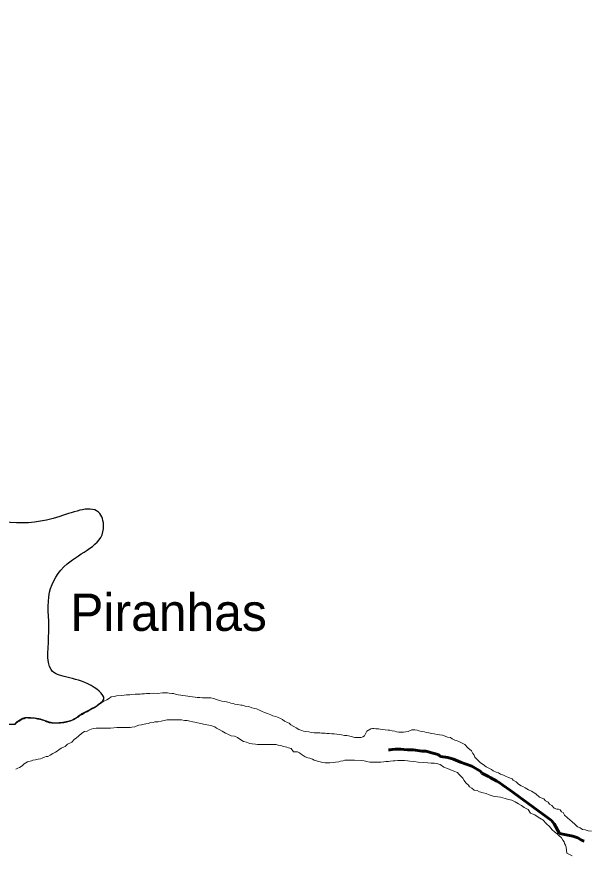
# Model space of a CAD drawing. Extents: x 553962 to 842807, y 8883888 to 9032388.
# Drawn here: x 635696 to 643403, y 8933785 to 8945035 of the extents above; entities that cross this region are included whole.
import ezdxf

# ---------------------------------------------------------------- set-up
doc = ezdxf.new("R2010")
doc.units = 0
doc.header["$LTSCALE"] = 200
doc.linetypes.add('LONG_DASH_SHORT_DASH', pattern=[9.9, 6, -1.2, 1.5, -1.2])
for name, color, linetype, lineweight in [('21', 7, 'Continuous', 25), ('25', 7, 'Continuous', 13), ('7', 7, 'Continuous', 90), ('9', 7, 'Continuous', 90)]:
    doc.layers.add(name, color=color, linetype=linetype, lineweight=lineweight)
doc.layers.add('41', color=7, linetype='Continuous')

msp = doc.modelspace()

# ---------------------------------------------------------------- linework, layer by layer
at = {"layer": '21'}
msp.add_spline([(635677.5, 8935542.3), (635110.6, 8935620.5), (634836.9, 8935855.3), (634709.8, 8936099.8), (634846.6, 8936275.8), (634973.7, 8936735.4), (635032.4, 8937263.6), (634739.1, 8937449.4), (634426.3, 8937517.8), (634700, 8937928.6), (634700, 8938261.1), (634533.8, 8938671.9), (634641.4, 8938906.6), (634768.4, 8938867.5), (634866.2, 8938740.3), (635130.1, 8938750.1), (635188.8, 8938564.3), (635325.6, 8938329.6), (635609.1, 8938251.3), (636273.8, 8938329.6), (636811.4, 8938368.7), (636860.3, 8938163.3), (636371.5, 8937693.9), (636136.9, 8937312.5), (636127.2, 8936784.3), (636156.5, 8936275.8), (636694.1, 8936060.6), (636850.5, 8935855.3), (636821.3, 8935831.4), (636756.6, 8935782.4), (636679.7, 8935742.2), (636611.5, 8935703.8), (636571.3, 8935684.5), (636504.8, 8935639.1), (636420.9, 8935593.6), (636337, 8935576.1), (636239.1, 8935562.1), (636151.7, 8935569.1), (636071.2, 8935593.6), (635990.8, 8935618.1), (635878.9, 8935632.1), (635826.5, 8935633.8), (635795, 8935628.6), (635758.3, 8935612.8), (635712.8, 8935584.8), (635680.9, 8935555.9), (635677.5, 8935542.3)], degree=3, dxfattribs=at)
at = {"layer": '25'}
for points in [[(635685.7, 8935554.4), (635710.8, 8935574.3), (635733.4, 8935581.6), (635756.1, 8935601.5), (635776.2, 8935611.4), (635796.2, 8935616.2), (635818.8, 8935626.1), (635848.8, 8935625.9), (635868.8, 8935625.8), (635908.8, 8935623), (635941.3, 8935617.8), (635973.8, 8935612.6), (636006.2, 8935604.8), (636036.2, 8935597.1), (636073.6, 8935586.9), (636096, 8935574.2), (636130.9, 8935559), (636165.9, 8935556.2), (636185.9, 8935556.1), (636205.9, 8935556), (636243.4, 8935555.7), (636263.5, 8935558.1), (636283.5, 8935557.9), (636303.5, 8935560.3), (636326, 8935562.7), (636346.1, 8935565), (636366.1, 8935569.9), (636398.7, 8935579.7), (636418.7, 8935582.1), (636456.4, 8935599.4), (636479, 8935616.7), (636519.2, 8935636.5), (636539.3, 8935653.9), (636579.5, 8935671.2), (636602.1, 8935691), (636642.3, 8935710.8), (636675, 8935730.6), (636712.6, 8935747.9), (636737.7, 8935762.7), (636770.4, 8935785.1), (636793.1, 8935802.4), (636835.8, 8935834.7), (636863.5, 8935852), (636906.1, 8935869.3), (636941.3, 8935891.6), (636964, 8935908.9), (637009, 8935916.2), (637036.6, 8935923.5), (637099.2, 8935928.1), (637136.7, 8935930.3), (637169.2, 8935935.1), (637214.3, 8935937.3), (637241.8, 8935942.2), (637284.4, 8935946.9), (637304.4, 8935946.8), (637351.9, 8935946.4), (637374.4, 8935948.8), (637412, 8935951.1), (637437, 8935953.4), (637479.5, 8935955.6), (637524.6, 8935960.3), (637584.6, 8935954.9), (637652.2, 8935962), (637672.2, 8935961.8), (637694.7, 8935961.7), (637719.7, 8935961.5), (637742.2, 8935958.9), (637777.1, 8935953.6), (637799.7, 8935953.5), (637824.6, 8935945.8), (637859.6, 8935938.1), (637897, 8935932.8), (637922, 8935927.6), (637959.5, 8935922.4), (637989.5, 8935917.2), (638012, 8935914.5)], [(638012, 8935914.5), (638051.9, 8935909.3), (638091.9, 8935904), (638116.9, 8935901.3), (638154.4, 8935901.1), (638186.9, 8935898.3), (638226.9, 8935895.6), (638259.4, 8935895.4), (638281.9, 8935895.2), (638301.9, 8935895.1), (638341.9, 8935887.3), (638376.8, 8935874.6), (638414.2, 8935861.8), (638449.2, 8935851.6), (638486.6, 8935846.3), (638509.1, 8935841.1), (638544.1, 8935835.9), (638566.5, 8935825.7), (638599, 8935820.5), (638621.5, 8935812.9), (638663.9, 8935805.1), (638701.4, 8935799.8), (638721.4, 8935799.7), (638761.3, 8935786.9), (638808.8, 8935779.1), (638851.2, 8935763.8), (638891.1, 8935753.5), (638913.6, 8935750.8), (638951, 8935733.1), (638978.4, 8935717.9), (639020.8, 8935700.1), (639058.2, 8935684.8), (639103.1, 8935669.5), (639130.5, 8935656.8), (639170.4, 8935646.5), (639195.4, 8935636.3), (639232.7, 8935618.6), (639260.2, 8935605.8), (639290, 8935583.1), (639327.4, 8935565.3), (639349.8, 8935555.2), (639374.7, 8935535), (639412, 8935512.2), (639444.4, 8935494.5), (639481.7, 8935471.7), (639519.2, 8935458.9), (639544.1, 8935451.3), (639576.6, 8935443.5), (639614, 8935438.3), (639646.5, 8935433.1), (639686.5, 8935427.8), (639719, 8935425.1), (639739, 8935424.9), (639761.5, 8935424.8), (639784, 8935422.1), (639814, 8935421.9), (639834, 8935421.8), (639856.5, 8935419.1), (639889, 8935416.4), (639921.5, 8935413.7), (639956.5, 8935413.5), (639991.5, 8935408.2), (640021.5, 8935405.5), (640053.9, 8935400.3), (640093.9, 8935392.5), (640126.4, 8935389.8), (640148.9, 8935384.7), (640183.8, 8935376.9), (640233.7, 8935364.2), (640316.3, 8935366), (640339.2, 8935375.1), (640361.5, 8935385.8), (640394.5, 8935450.6), (640447.2, 8935480.3), (640467.3, 8935485.2), (640487.3, 8935485.1), (640514.8, 8935482.4), (640549.8, 8935479.7), (640572.2, 8935474.5), (640607.2, 8935471.8), (640639.7, 8935466.5), (640677.2, 8935463.8), (640699.7, 8935461.1), (640732.2, 8935455.9), (640767.1, 8935450.7), (640789.6, 8935440.5), (640822, 8935435.3), (640842.1, 8935435.2), (640864.6, 8935435), (640884.6, 8935434.9), (640947.2, 8935447), (640994.9, 8935466.7), (641014.9, 8935466.6), (641037.4, 8935466.4), (641067.3, 8935461.2), (641089.8, 8935453.6), (641132.3, 8935445.8), (641167.2, 8935440.5), (641189.7, 8935432.8), (641224.7, 8935427.6), (641259.6, 8935419.9)], [(638992.5, 8935272.2), (638970, 8935272.3), (638925, 8935272.6), (638897.5, 8935275.3), (638855, 8935278.1), (638825, 8935285.8), (638777.6, 8935303.6), (638737.7, 8935311.4), (638700.3, 8935331.7), (638658.1, 8935364.5), (638618.2, 8935382.3), (638573.2, 8935387.6), (638535.8, 8935402.8), (638495.9, 8935423.1), (638451.1, 8935451), (638413.8, 8935471.2), (638376.4, 8935489), (638351.5, 8935506.7), (638314.1, 8935522), (638274.1, 8935529.8), (638224.2, 8935537.6), (638161.8, 8935553), (638086.8, 8935568.6), (638059.4, 8935576.2), (638019.4, 8935581.5), (637982, 8935591.8), (637947, 8935594.5), (637907, 8935599.8), (637884.5, 8935599.9), (637847, 8935600.2), (637827, 8935600.3), (637792, 8935600.5), (637754.5, 8935600.8), (637714.4, 8935601.1), (637691.9, 8935596.2), (637654.3, 8935588.9), (637631.8, 8935584.1), (637591.7, 8935576.8), (637549.2, 8935574.6), (637524.1, 8935567.3), (637481.5, 8935560), (637461.5, 8935552.7), (637426.4, 8935547.9), (637406.4, 8935543), (637371.3, 8935535.7), (637336.2, 8935528.4), (637298.6, 8935516.2), (637278.5, 8935508.8), (637238.5, 8935504.1), (637215.9, 8935499.2), (637180.9, 8935499.4), (637135.9, 8935499.7), (637105.9, 8935499.9), (637063.4, 8935500.2), (637040.8, 8935497.9), (637000.8, 8935493.1), (636955.8, 8935490.9), (636930.8, 8935491.1), (636890.7, 8935488.8), (636868.2, 8935489), (636830.7, 8935489.2), (636810.7, 8935489.4), (636780.7, 8935489.6), (636760.7, 8935489.7), (636725.6, 8935484.9), (636693, 8935475.1), (636673, 8935467.8), (636640.3, 8935447.9), (636605.2, 8935443.2), (636567.6, 8935420.9), (636524.7, 8935381.1), (636499.6, 8935358.7), (636466.9, 8935336.4), (636436.6, 8935301.6), (636416.5, 8935294.2), (636378.9, 8935276.9), (636343.6, 8935244.6), (636323.5, 8935234.7), (636293.4, 8935219.9), (636260.8, 8935200.1), (636238.1, 8935180.2), (636215.5, 8935167.8), (636180.3, 8935148.1), (636142.7, 8935128.3), (636112.5, 8935110.9), (636092.5, 8935108.6), (636069.9, 8935098.7), (636037.3, 8935088.9), (636014.7, 8935079.1), (635982.2, 8935074.3), (635947.1, 8935067), (635912, 8935059.7), (635892, 8935052.3), (635859.4, 8935042.5), (635839.3, 8935037.7), (635816.7, 8935025.3), (635794.1, 8935010.4), (635773.9, 8934990.5), (635753.8, 8934975.6), (635731.2, 8934963.3), (635708.6, 8934950.9)], [(641259.6, 8935419.9), (641294.6, 8935414.6), (641334.5, 8935404.4), (641369.5, 8935399.1), (641409.5, 8935393.8), (641441.9, 8935383.6), (641474.3, 8935368.4), (641514.3, 8935363.1), (641536.7, 8935345.4), (641574.1, 8935330.2), (641596.6, 8935325), (641636.4, 8935307.2), (641673.8, 8935289.5), (641708.7, 8935271.7), (641748.3, 8935223.9), (641798.1, 8935183.5), (641812.8, 8935148.3), (641832.6, 8935125.7), (641842.5, 8935100.6), (641872.2, 8935067.8), (641894.6, 8935047.7), (641916.9, 8935022.5), (641954.2, 8935002.2), (641994, 8934971.9), (642028.9, 8934954.1), (642063.8, 8934936.4), (642086.2, 8934918.7), (642126, 8934898.4), (642161, 8934890.7), (642188.4, 8934873), (642225.8, 8934860.2), (642260.7, 8934842.4), (642283.1, 8934832.3), (642318, 8934819.5), (642340.5, 8934811.9), (642357.8, 8934791.7), (642395.2, 8934769), (642427.4, 8934736.2), (642462.3, 8934715.9), (642484.8, 8934708.3), (642517.1, 8934690.5), (642539.5, 8934675.4), (642561.9, 8934660.2), (642604.3, 8934642.4), (642661.6, 8934609.5), (642711.2, 8934564.1), (642766.1, 8934543.7), (642790.9, 8934513.5), (642825.8, 8934495.7), (642845.6, 8934470.6), (642875.5, 8934450.3), (642907.7, 8934417.6), (642942.6, 8934402.3), (642965.1, 8934402.2), (642987.6, 8934394.5), (643004.9, 8934366.9), (643027.3, 8934356.7), (643044.6, 8934324), (643084.3, 8934286.2), (643146.4, 8934233.2), (643183.7, 8934202.9), (643221, 8934167.7), (643253.4, 8934152.4), (643288.2, 8934132.2), (643323.2, 8934124.4), (643363.1, 8934114.1), (643405.6, 8934108.8)], [(642690, 8934297.2), (642645.2, 8934327.5), (642587.9, 8934347.9), (642556.4, 8934400.2), (642504.8, 8934424.3), (642466.9, 8934451.8), (642425.6, 8934475.9), (642384.3, 8934503.4), (642339.5, 8934524.1), (642294.8, 8934534.4), (642294.8, 8934534.4), (642246.6, 8934548.2), (642188.1, 8934561.9), (642151.8, 8934566.1), (642086.9, 8934579), (642032, 8934596.9), (641994.6, 8934612.2), (641952.2, 8934620), (641902.2, 8934635.3), (641874.9, 8934653.1), (641834.9, 8934658.3), (641800.1, 8934686.1), (641770.2, 8934701.3), (641755.4, 8934726.4), (641723.1, 8934756.7), (641698.3, 8934789.4), (641681, 8934817.1), (641663.7, 8934837.2), (641628.9, 8934872.5), (641609.1, 8934892.6), (641558.1, 8934912.8), (641506.5, 8934933.5), (641473.6, 8934950.3), (641426.3, 8934968.1), (641376.5, 8935001), (641329.1, 8935016.3), (641301.6, 8935019), (641254.1, 8935021.8), (641209.1, 8935024.7), (641159.1, 8935027.5), (641081.6, 8935035.5), (641021.6, 8935040.9), (640971.7, 8935046.2), (640936.7, 8935051.5), (640899.2, 8935054.2), (640864.2, 8935054.5), (640841.7, 8935054.6), (640806.6, 8935054.8), (640769.1, 8935052.6), (640744.1, 8935050.3), (640704, 8935048), (640684, 8935043.2), (640649, 8935040.9), (640621.4, 8935036.1), (640578.9, 8935033.8), (640543.8, 8935031.6), (640498.8, 8935031.8), (640471.3, 8935032), (640451.3, 8935032.2), (640431.3, 8935032.3), (640393.9, 8935042.6), (640358.9, 8935052.8), (640326.5, 8935058), (640229.1, 8935058.3), (640168.9, 8935061.6), (640141.4, 8935061.8), (640098.9, 8935059.5), (640076.3, 8935052.2), (640041.2, 8935047.4), (640016.2, 8935040.1), (639971.1, 8935032.8), (639951.1, 8935028), (639898.5, 8935025.8), (639856, 8935026.1), (639833.5, 8935026.2), (639801, 8935029), (639768.6, 8935039.2), (639738.6, 8935044.4), (639708.7, 8935054.6), (639686.2, 8935062.3), (639663.8, 8935072.4), (639628.9, 8935085.2), (639601.4, 8935090.4), (639564, 8935105.6), (639536.6, 8935120.8), (639511.7, 8935141), (639489.3, 8935158.7), (639464.5, 8935173.9), (639409.4, 8935171.8), (639379.8, 8935217), (639342.3, 8935227.3), (639317.4, 8935234.9), (639274.9, 8935242.7), (639240, 8935255.5), (639202.5, 8935263.2), (639177.6, 8935270.9), (639125.1, 8935271.3), (639090, 8935271.5), (639050, 8935271.8), (639030, 8935271.9), (638992.5, 8935272.2)], [(635708.6, 8934950.9), (635686, 8934941)], [(643148, 8933777.6), (643078.2, 8933813.1), (643066.3, 8933890.8), (643056.5, 8933918.4), (643046.7, 8933941), (643039.3, 8933966.1), (643022, 8933986.2), (643004.7, 8934016.4), (642970, 8934051.7), (642947.6, 8934071.8), (642910.3, 8934099.6), (642880.5, 8934127.3), (642842.1, 8934169.7), (642842.1, 8934169.7), (642804.3, 8934207.6), (642755, 8934260.3), (642734.8, 8934269.3), (642690, 8934297.2)]]:
    msp.add_lwpolyline(points, dxfattribs=at)
at = {"layer": '7', "linetype": 'LONG_DASH_SHORT_DASH', "lineweight": 60}
for points in [[(641349.5, 8935138.5), (641279.6, 8935153.8), (641232.2, 8935166.6), (641182.2, 8935179.4), (641137.2, 8935182.1), (641014.8, 8935197.8), (640987.4, 8935200.4), (640937.4, 8935200.7), (640887.4, 8935203.5), (640847.4, 8935206.2), (640824.9, 8935206.3), (640794.9, 8935206.5), (640772.4, 8935206.6), (640732.4, 8935204.3), (640707.4, 8935199.4), (640683.2, 8935198.4)], [(643306.9, 8933971.4), (643271.7, 8933987.2), (643222, 8934017.5), (643154.6, 8934040.4), (642977.3, 8934076.3), (642905.7, 8934204.3), (642868.5, 8934249.6), (642368.5, 8934617.6), (642318.7, 8934652.9), (642216.7, 8934723.5), (642166.9, 8934758.8), (642137, 8934776.5), (642047.4, 8934827), (642025, 8934842.1), (641937.8, 8934885.1), (641922.9, 8934907.7), (641800.9, 8934978.4), (641648.8, 8935034.3), (641556.5, 8935072.3), (641479.2, 8935095.2), (641381.8, 8935110.8), (641349.5, 8935138.5)]]:
    msp.add_lwpolyline(points, dxfattribs=at)
at = {"layer": '9'}
msp.add_spline([(637260.6, 8972975.8), (641524.5, 8971056.2), (652526.1, 8965412.7), (653164.3, 8965062.8), (670790.5, 8953770.1), (686194, 8943929.9), (696283.3, 8937647.1)], degree=3, dxfattribs=at)

# ---------------------------------------------------------------- texts
at = {"layer": '41'}
msp.add_text('Piranhas', height=500, dxfattribs=at).set_placement((636412.8, 8936794.9))

doc.saveas('drawing.dxf')
